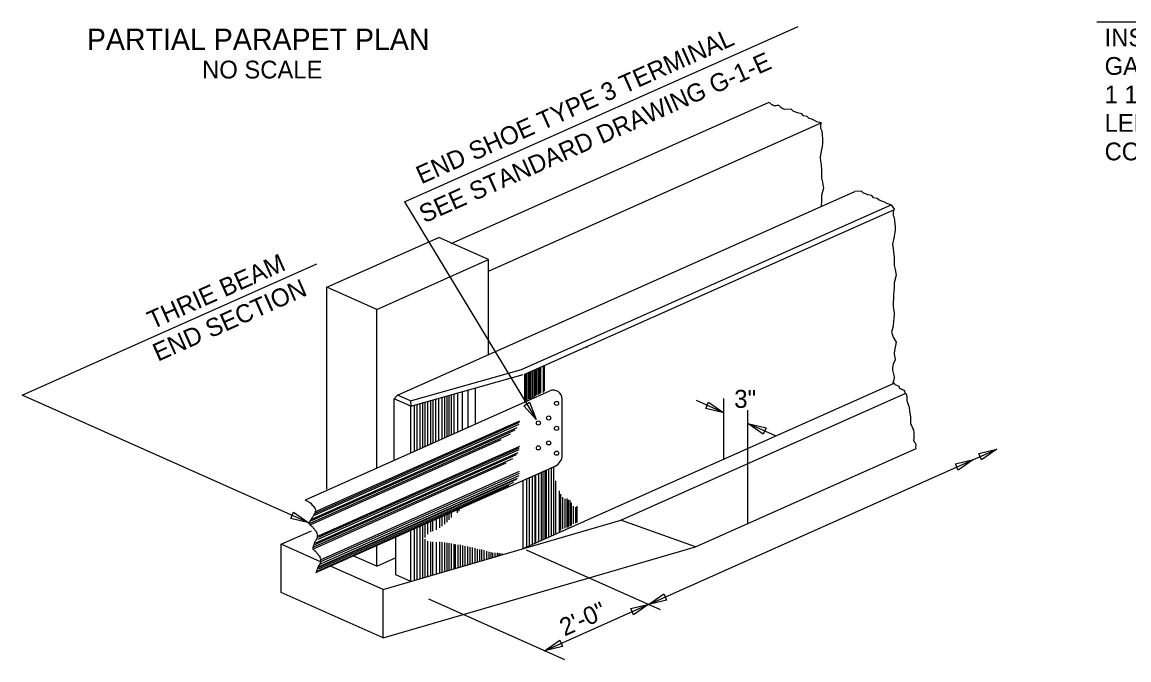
# Model space of a CAD drawing. Extents: x 0 to 34.5, y 0 to 23.5.
# Drawn here: x 9.41 to 19.13, y 6.84 to 12.44 of the extents above; entities that cross this region are included whole.
import ezdxf

# ---------------------------------------------------------------- set-up
doc = ezdxf.new("R2010")
doc.units = 0
doc.layers.add('BRDG_ANNO_General-Notes', color=7, linetype='Continuous')
doc.layers.add('BRDG_BASE_Obj-Line', color=7, linetype='Continuous')

msp = doc.modelspace()

# ---------------------------------------------------------------- linework, layer by layer
at = {"layer": 'BRDG_ANNO_General-Notes'}
for p, q in [((12.767, 10.8593), (16.2252, 12.399)), ((21.2758, 12.4362), (18.8479, 12.4362)), ((12.767, 10.8593), (13.9234, 8.947)), ((9.4092, 9.1629), (11.9988, 10.316)), ((11.9264, 8.0415), (9.4092, 9.1629)), ((13.815, 9.0684), (13.8663, 9.0995)), ((13.9234, 8.947), (13.815, 9.0684)), ((13.8663, 9.0995), (13.9234, 8.947)), ((15.5719, 9.0077), (15.3311, 9.1149)), ((15.4136, 9.0454), (15.438, 9.1002)), ((15.5719, 9.0077), (15.4136, 9.0454)), ((15.438, 9.1002), (15.5719, 9.0077)), ((15.5719, 8.5945), (15.5719, 9.1331)), ((15.7842, 8.03), (15.7842, 9.0311)), ((16.0259, 8.8054), (15.7842, 8.9131)), ((15.9182, 8.8206), (15.7842, 8.9131)), ((15.7842, 8.9131), (15.9426, 8.8754)), ((15.9426, 8.8754), (15.9182, 8.8206)), ((14.9104, 7.3255), (17.969, 8.6873)), ((17.8106, 8.6496), (17.969, 8.6873)), ((17.969, 8.6873), (17.8351, 8.5948)), ((17.6055, 8.5583), (17.7638, 8.5959)), ((17.6299, 8.5035), (17.6055, 8.5583)), ((17.7638, 8.5959), (17.6299, 8.5035)), ((17.8351, 8.5948), (17.8106, 8.6496)), ((11.768, 8.0792), (11.7925, 8.134)), ((11.9264, 8.0415), (11.768, 8.0792)), ((11.7925, 8.134), (11.9264, 8.0415)), ((15.0164, 7.2782), (13.8391, 7.8027)), ((14.9104, 7.3255), (15.0443, 7.418)), ((15.0443, 7.418), (15.0687, 7.3632)), ((14.1745, 6.8388), (12.9802, 7.3707)), ((13.9965, 6.9186), (14.913, 7.3267)), ((14.7547, 7.289), (14.913, 7.3267)), ((14.913, 7.3267), (14.7791, 7.2342)), ((15.0687, 7.3632), (14.9104, 7.3255)), ((14.7791, 7.2342), (14.7547, 7.289)), ((13.9965, 6.9186), (14.1305, 7.0111)), ((14.1305, 7.0111), (14.1549, 6.9563)), ((14.1549, 6.9563), (13.9965, 6.9186))]:
    msp.add_line(p, q, dxfattribs=at)
msp.add_spline([(16.1074, 11.6688), (16.0729, 11.6863), (16.0546, 11.7036), (16.019, 11.7005), (15.9915, 11.7148), (15.9652, 11.7321)], degree=3, dxfattribs=at)
at = {"layer": 'BRDG_BASE_Obj-Line'}
for p, q in [((13.1777, 10.4944), (15.9652, 11.7321)), ((16.1639, 11.6712), (16.1074, 11.6688)), ((16.1812, 11.6558), (16.1639, 11.6712)), ((16.2205, 11.639), (16.1812, 11.6558)), ((16.2573, 11.6319), (16.2205, 11.639)), ((16.2717, 11.6127), (16.2573, 11.6319)), ((16.3028, 11.6074), (16.2717, 11.6127)), ((16.3205, 11.5917), (16.3028, 11.6074)), ((16.3435, 11.5835), (16.3205, 11.5917)), ((16.3674, 11.5739), (16.3435, 11.5835)), ((16.3875, 11.562), (16.3674, 11.5739)), ((13.5043, 10.251), (16.4266, 11.5521)), ((16.4266, 11.5521), (16.3875, 11.562)), ((12.7071, 9.1623), (16.7235, 10.9505)), ((16.7799, 10.9529), (16.7235, 10.9505)), ((16.7972, 10.9374), (16.7799, 10.9529)), ((16.8365, 10.9207), (16.7972, 10.9374)), ((16.8733, 10.9135), (16.8365, 10.9207)), ((16.8877, 10.8944), (16.8733, 10.9135)), ((16.9188, 10.8891), (16.8877, 10.8944)), ((16.9365, 10.8733), (16.9188, 10.8891)), ((13.796, 9.3883), (17.0426, 10.8338)), ((13.8232, 9.3468), (17.0697, 10.7922)), ((16.9595, 10.8652), (16.9365, 10.8733)), ((16.9834, 10.8556), (16.9595, 10.8652)), ((17.0035, 10.8436), (16.9834, 10.8556)), ((17.0426, 10.8338), (17.0035, 10.8436)), ((17.0426, 10.8338), (17.0697, 10.7922)), ((12.0849, 10.1096), (13.0678, 10.546)), ((13.5046, 10.3517), (13.0678, 10.546)), ((12.5231, 9.9147), (13.5046, 10.3517)), ((13.5046, 9.5164), (13.5046, 10.3517)), ((12.5231, 9.9147), (12.0849, 10.1096)), ((12.0849, 8.3363), (12.0849, 10.1096)), ((12.5231, 8.5202), (12.5231, 9.9147)), ((14.3656, 9.5887), (14.3678, 9.5801)), ((12.8189, 9.1127), (13.796, 9.3883)), ((12.8231, 9.0652), (13.8087, 9.3432)), ((13.8232, 9.1029), (13.8232, 9.3468)), ((13.8334, 9.1083), (13.8334, 9.3518)), ((13.8437, 9.1177), (13.8437, 9.3564)), ((13.8593, 9.127), (13.8593, 9.3633)), ((13.8718, 9.1302), (13.8718, 9.3689)), ((13.8811, 9.1333), (13.8811, 9.3731)), ((13.8936, 9.1395), (13.8936, 9.3786)), ((13.9092, 9.1458), (13.9092, 9.3856)), ((13.9217, 9.1552), (13.9217, 9.3911)), ((13.931, 9.1645), (13.931, 9.3953)), ((13.9435, 9.1676), (13.9435, 9.4008)), ((13.9529, 9.1707), (13.9529, 9.4051)), ((13.9654, 9.1801), (13.9654, 9.4106)), ((13.9872, 9.1864), (13.9872, 9.4203)), ((13.9966, 9.1957), (13.9966, 9.4245)), ((13.8084, 7.8166), (17.0671, 9.2677)), ((11.8972, 8.2435), (14.0428, 9.1989)), ((12.7071, 9.1623), (12.6756, 9.1308)), ((12.8189, 9.1127), (12.7071, 9.1623)), ((13.0978, 8.7757), (13.0978, 9.1427)), ((13.1228, 8.7871), (13.1228, 9.1497)), ((13.1415, 8.7957), (13.1415, 9.155)), ((13.1602, 8.8043), (13.1602, 9.1603)), ((13.179, 8.8129), (13.179, 9.1656)), ((13.2039, 8.8244), (13.2039, 9.1726)), ((13.2357, 8.8419), (13.2357, 9.1816)), ((13.2755, 8.8642), (13.2755, 9.1928)), ((13.3274, 8.884), (13.3274, 9.2074)), ((13.3918, 8.9119), (13.3918, 9.2256)), ((14.6681, 8.0648), (17.1693, 9.1786)), ((12.6756, 8.5969), (12.6756, 9.1308)), ((12.8231, 9.0652), (12.6756, 9.1308)), ((12.8189, 9.1127), (12.8231, 9.0652)), ((12.8231, 8.6574), (12.8231, 9.0652)), ((12.8544, 8.673), (12.8544, 9.074)), ((12.8794, 8.6853), (12.8794, 9.081)), ((12.9043, 8.6949), (12.9043, 9.0881)), ((12.9293, 8.7052), (12.9293, 9.0951)), ((12.948, 8.712), (12.948, 9.1004)), ((12.973, 8.7235), (12.973, 9.1074)), ((12.9979, 8.7351), (12.9979, 9.1145)), ((13.0194, 8.7422), (13.0194, 9.1205)), ((13.0427, 8.7531), (13.0427, 9.1271)), ((13.0687, 8.7663), (13.0687, 9.1345)), ((14.1527, 8.6353), (14.1527, 9.1276)), ((11.9437, 8.0589), (13.7401, 8.8587)), ((11.9593, 8.0776), (13.7557, 8.8773)), ((11.9781, 8.1088), (13.7744, 8.9086)), ((11.9812, 8.1369), (13.7802, 8.9378)), ((11.9812, 8.1244), (13.7776, 8.9242)), ((11.9344, 8.037), (13.699, 8.8227)), ((11.9375, 8.0245), (13.6165, 8.772)), ((11.9897, 7.8673), (13.7648, 8.6577)), ((12.0085, 7.8986), (13.7758, 8.6855)), ((12.0116, 7.9267), (13.7791, 8.7136)), ((12.0116, 7.9142), (13.7757, 8.6996)), ((15.3245, 7.832), (17.2603, 8.694)), ((11.9648, 7.8268), (13.7177, 8.6072)), ((11.9679, 7.8143), (13.6615, 8.5684)), ((11.9742, 7.8486), (13.7518, 8.6402)), ((11.9892, 7.6044), (14.0909, 8.5402)), ((12.0303, 7.7176), (13.7789, 8.4961)), ((12.0396, 7.7051), (13.7771, 8.4786)), ((13.9155, 7.8604), (13.9155, 8.462)), ((13.9217, 7.8632), (13.9217, 8.4648)), ((13.9467, 7.874), (13.9467, 8.476)), ((13.9717, 7.8849), (13.9717, 8.4871)), ((13.9842, 7.8903), (13.9842, 8.4927)), ((14.0029, 7.8984), (14.0029, 8.501)), ((14.0154, 7.9068), (14.0154, 8.5065)), ((14.0341, 7.913), (14.0341, 8.5149)), ((14.0591, 7.9255), (14.0591, 8.526)), ((14.0778, 7.938), (14.0778, 8.5343)), ((12.0085, 7.6208), (13.688, 8.3686)), ((12.0116, 7.6489), (13.7517, 8.4236)), ((12.0147, 7.6364), (13.7267, 8.3987)), ((12.0179, 7.6582), (13.7594, 8.4336)), ((12.0303, 7.6801), (13.7736, 8.4563)), ((13.8094, 7.8143), (13.8094, 8.4148)), ((13.8416, 7.8306), (13.8416, 8.4315)), ((13.8656, 7.8388), (13.8656, 8.4398)), ((13.8906, 7.8496), (13.8906, 8.451)), ((14.0966, 7.9505), (14.0966, 8.4098)), ((14.1277, 7.963), (14.1277, 8.3227)), ((14.1402, 7.9755), (14.1402, 8.2926)), ((14.1589, 7.988), (14.1589, 8.2671)), ((14.1777, 7.9942), (14.1777, 8.2535)), ((14.1964, 8.0005), (14.1964, 8.2536)), ((14.2073, 8.002), (14.2073, 8.2429)), ((14.2214, 8.0129), (14.2214, 8.2415)), ((14.2339, 8.0192), (14.2339, 8.2181)), ((14.2526, 8.0317), (14.2526, 8.1867)), ((14.2713, 8.0379), (14.2713, 8.1794)), ((14.2838, 8.0442), (14.2838, 8.1878)), ((13.0479, 7.9813), (13.0479, 8.0749)), ((13.0791, 7.9984), (13.0791, 8.0886)), ((13.0978, 8.0122), (13.0978, 8.0968)), ((13.1228, 8.0301), (13.1228, 8.1078)), ((13.1415, 8.0485), (13.1415, 8.1161)), ((13.1602, 8.0682), (13.1602, 8.1243)), ((13.179, 8.0879), (13.179, 8.1326)), ((13.2343, 8.1305), (13.2343, 8.159)), ((13.2468, 8.1443), (13.2468, 8.1644)), ((11.6852, 7.8535), (11.9499, 7.9714)), ((12.579, 7.4554), (14.6681, 8.0648)), ((12.8231, 7.5266), (12.8231, 7.9757)), ((12.8544, 7.5357), (12.8544, 7.9896)), ((12.8794, 7.543), (12.8794, 8.0007)), ((12.9043, 7.8619), (12.9043, 8.0117)), ((12.9293, 7.891), (12.9293, 8.0228)), ((12.948, 7.9129), (12.948, 8.0309)), ((12.973, 7.9433), (12.973, 8.0419)), ((12.9979, 7.9613), (12.9979, 8.0529)), ((13.0167, 7.9693), (13.0167, 8.0611)), ((15.3245, 7.8319), (14.6681, 8.0648)), ((12.692, 7.585), (12.692, 7.9173)), ((12.9043, 7.5503), (12.9043, 7.9478)), ((12.9293, 7.5576), (12.9293, 7.8965)), ((12.948, 7.563), (12.948, 7.8976)), ((12.973, 7.5703), (12.973, 7.8813)), ((12.9979, 7.5776), (12.9979, 7.8753)), ((13.0791, 7.6013), (13.0791, 7.8755)), ((11.6852, 7.4296), (11.6852, 7.8535)), ((12.0297, 7.7), (11.6852, 7.8535)), ((12.5231, 7.6603), (12.5231, 7.8409)), ((12.5796, 7.0312), (15.3245, 7.8319)), ((13.0167, 7.5831), (13.0167, 7.8733)), ((13.0479, 7.5922), (13.0479, 7.8713)), ((13.0978, 7.6067), (13.0978, 7.8711)), ((13.1228, 7.614), (13.1228, 7.8684)), ((13.1415, 7.6195), (13.1415, 7.8651)), ((13.1602, 7.6249), (13.1602, 7.8619)), ((13.179, 7.6304), (13.179, 7.8586)), ((13.2039, 7.6377), (13.2039, 7.8536)), ((13.2164, 7.6414), (13.2164, 7.8504)), ((13.2381, 7.6468), (13.2381, 7.8497)), ((13.2587, 7.6566), (13.2587, 7.8479)), ((13.2793, 7.6631), (13.2793, 7.8417)), ((13.2999, 7.6663), (13.2999, 7.8357)), ((13.3238, 7.6739), (13.3238, 7.8328)), ((13.3433, 7.6793), (13.3433, 7.8286)), ((13.3661, 7.6815), (13.3661, 7.8237)), ((13.3878, 7.6891), (13.3878, 7.8191)), ((13.4095, 7.6967), (13.4095, 7.8116)), ((13.4301, 7.701), (13.4301, 7.8088)), ((13.4464, 7.7076), (13.4464, 7.8063)), ((13.4659, 7.7151), (13.4659, 7.8008)), ((13.4919, 7.7216), (13.4919, 7.7932)), ((13.5104, 7.7292), (13.5104, 7.7878)), ((13.5277, 7.7314), (13.5277, 7.7829)), ((13.5429, 7.7346), (13.5429, 7.7789)), ((13.5646, 7.7422), (13.5646, 7.7768)), ((13.5852, 7.7477), (13.5852, 7.7768)), ((12.5231, 7.6603), (12.3216, 7.75)), ((12.5231, 7.6603), (12.6941, 7.7364)), ((13.5993, 7.7574), (13.5993, 7.7749)), ((13.6091, 7.7553), (13.6091, 7.7735)), ((13.6254, 7.7564), (13.6254, 7.7723)), ((12.579, 7.4554), (12.1236, 7.6582)), ((12.8231, 7.5266), (12.692, 7.585)), ((12.5796, 7.0312), (11.6852, 7.4296)), ((12.5796, 7.0312), (12.5796, 7.4533))]:
    msp.add_line(p, q, dxfattribs=at)
for points in [[(16.4266, 11.5521), (16.4222, 11.5348), (16.4222, 11.5044), (16.4309, 11.487), (16.4352, 11.4567), (16.4396, 11.4046), (16.4396, 11.3742), (16.4352, 11.3439), (16.4309, 11.3178), (16.4179, 11.2527), (16.4179, 11.2484), (16.4222, 11.218), (16.4266, 11.1833), (16.4309, 11.1356), (16.4309, 11.0661), (16.4396, 11.0314), (16.4482, 10.9793), (16.4309, 10.9142), (16.4309, 10.8708), (16.4271, 10.8181)], [(17.0629, 10.7867), (17.0585, 10.7693), (17.0585, 10.7389), (17.0672, 10.7216), (17.0715, 10.6912), (17.0759, 10.6391), (17.0759, 10.6087), (17.0715, 10.5784), (17.0672, 10.5523), (17.0542, 10.4872), (17.0542, 10.4829), (17.0585, 10.4526), (17.0629, 10.4178), (17.0672, 10.3701), (17.0672, 10.3006), (17.0759, 10.2659), (17.0845, 10.2139), (17.0672, 10.1487), (17.0672, 10.1054), (17.0629, 10.0446), (17.0629, 10.0143), (17.0585, 9.9752), (17.0585, 9.9448), (17.0629, 9.9144), (17.0672, 9.8884), (17.0672, 9.8667), (17.0585, 9.7799), (17.0585, 9.7669), (17.0455, 9.7148), (17.0542, 9.6888), (17.0585, 9.6715), (17.0845, 9.628), (17.0759, 9.5846), (17.0715, 9.5543), (17.0672, 9.5282), (17.0759, 9.4718), (17.0585, 9.4328), (17.0542, 9.4024), (17.0542, 9.3807), (17.0585, 9.359), (17.0672, 9.3243), (17.0672, 9.3156), (17.0629, 9.2852), (17.0542, 9.2722), (17.0671, 9.2677)], [(17.0672, 9.2679), (17.0737, 9.257), (17.0824, 9.2527), (17.0976, 9.2461), (17.1084, 9.2397), (17.1128, 9.2267), (17.1193, 9.2245), (17.128, 9.218), (17.1388, 9.2136), (17.1474, 9.2093), (17.1518, 9.2049), (17.1583, 9.1962), (17.1605, 9.1876), (17.1627, 9.1767), (17.1648, 9.1767), (17.1714, 9.1789), (17.1779, 9.1529), (17.1779, 9.1355), (17.18, 9.116), (17.1822, 9.103), (17.1887, 9.0878), (17.1909, 9.0791), (17.1995, 9.0574), (17.2039, 9.0205), (17.2104, 8.9706), (17.2126, 8.9337), (17.2126, 8.9098), (17.2191, 8.8947), (17.2299, 8.873), (17.2386, 8.8578), (17.2408, 8.8296), (17.2408, 8.7949), (17.2408, 8.7819), (17.2386, 8.7667), (17.2451, 8.7515), (17.2559, 8.7406), (17.2581, 8.7233), (17.2559, 8.7059), (17.2581, 8.6951), (17.2624, 8.6907)]]:
    msp.add_lwpolyline(points, dxfattribs=at)
for centre in [(14.1028, 9.0896), (14.0341, 8.9617), (13.9436, 8.918), (14.1028, 8.8711), (14.0341, 8.7429), (13.9436, 8.6992), (14.1028, 8.6524)]:
    msp.add_circle(centre, 0.0182, dxfattribs=at)
for centre, radius, start, end in [((14.0746, 9.1275), 0.0781, 0, 114.00031), ((14.0485, 8.6353), 0.1042, 293.99964, 0)]:
    msp.add_arc(centre, radius, start, end, dxfattribs=at)
for points in [[(11.8964, 8.2426), (11.9245, 8.227), (11.937, 8.2207), (11.9495, 8.2051), (11.9651, 8.1895), (11.9776, 8.174), (11.9869, 8.1521), (11.9869, 8.1396), (11.9807, 8.1271), (11.9744, 8.1178), (11.9682, 8.1053), (11.9619, 8.0928), (11.9526, 8.0834), (11.9495, 8.0741), (11.9401, 8.0616), (11.937, 8.0553), (11.9307, 8.0428), (11.9307, 8.0334), (11.9339, 8.0272), (11.9432, 8.021), (11.9495, 8.0116), (11.9557, 8.0085), (11.9619, 8.0022), (11.9682, 7.9929), (11.9776, 7.9835), (11.9838, 7.9742), (11.9932, 7.9648), (11.9963, 7.9492), (12.0026, 7.9398), (11.9994, 7.9274), (11.9994, 7.9118), (11.9963, 7.9024), (11.9932, 7.893), (11.9838, 7.8805), (11.9744, 7.8587), (11.9744, 7.8556), (11.9682, 7.8431), (11.9651, 7.8274), (11.9619, 7.8213)], [(11.9599, 7.8173), (11.9599, 7.8165), (11.9631, 7.8103), (11.9724, 7.804), (11.9787, 7.7946), (11.9849, 7.7915), (11.9911, 7.7853), (11.9974, 7.7759), (12.0068, 7.7665), (12.013, 7.7572), (12.0224, 7.7479), (12.0255, 7.7322), (12.0318, 7.7229), (12.0286, 7.7104), (12.0286, 7.6948), (12.0255, 7.6854), (12.0224, 7.676), (12.013, 7.6635), (12.0036, 7.6417), (12.0036, 7.6386), (11.9974, 7.6261), (11.9943, 7.6105), (11.9911, 7.6043)]]:
    msp.add_spline(points, degree=3, dxfattribs=at)

# ---------------------------------------------------------------- texts
at = {"layer": 'BRDG_ANNO_General-Notes'}
for s, height, p in [('PARTIAL PARAPET PLAN', 0.1875, (9.9775, 12.1918)), ('INSERTS WITH', 0.15625, (18.9166, 12.2235)), ('NO SCALE', 0.15625, (10.9899, 11.9418)), ('GALV.  BOLTS', 0.15625, (18.9166, 11.9735)), ('1 1/2" MINIMUM', 0.15625, (18.9166, 11.7235)), ('LENGTH IN', 0.15625, (18.9166, 11.4735)), ('CONCRETE', 0.15625, (18.9166, 11.2235)), ('3"', 0.15833, (15.6629, 9.0504))]:
    msp.add_text(s, height=height, dxfattribs=at).set_placement(p)
for s, height, rotation, p in [('END SHOE TYPE 3 TERMINAL', 0.158333, 24.00033, (12.9146, 11.0121)), ('SEE STANDARD DRAWING G-1-E', 0.158333, 24.00033, (12.9408, 10.6697)), ('THRIE BEAM', 0.15833, 24.00122, (10.5536, 9.7384)), ('END SECTION', 0.158333, 24.00122, (10.6017, 9.4549)), ('2\'-0"', 0.15625, 24.00084, (14.1737, 7.0433))]:
    msp.add_text(s, height=height, rotation=rotation, dxfattribs=at).set_placement(p)

doc.saveas('drawing.dxf')
